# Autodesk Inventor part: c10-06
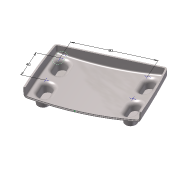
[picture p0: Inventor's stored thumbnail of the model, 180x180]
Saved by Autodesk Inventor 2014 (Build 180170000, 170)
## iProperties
Created: 2010-12
Part Number: c10-06
Material: Generic
Document SubType Name: Modeling
Designer: Thom Tremblay
Density: 1 g/cm^3
Appearance: Generic
Author: Thom Tremblay
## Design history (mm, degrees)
sketch "Sketch1"
  geometry: L1 (-60, -12)-(60, -12); L2 (60, -12)-(60, 12); L3 (60, 12)-(-60, 12); L4 (-60, 12)-(-60, -12); A1 r 350 centre (0, -332.819) between (60, 12) and (-60, 12); A2 r 350 centre (0, 332.819) between (-60, -12) and (60, -12); 3 further points
  constraints: 8 end point, 4 point on circle, 2 centre point, 2 midpoint, 2 parallel, 1 equal radius, 1 horizontal, 1 horizontal alignment, 1 perpendicular, 1 vertical alignment
  dimensions: "d0" = 120 distance of L3.end L2.end; "d1" = 24 distance of L2.end L1.end; "d2" = 350 radius of A1
workplane "Work Plane4"
sketch "Sketch5"
  geometry: L1 (-60, 12)-(-60, -12) reference; L2 (60, -12)-(60, 12) reference; L3 (-58, 10.314)-(-58, -10.314); L4 (58, -10.314)-(58, 10.314); A1 r 350 centre (0, 332.819) between (-60, -12) and (60, -12) reference; A2 r 350 centre (0, -332.819) between (60, 12) and (-60, 12) reference; A3 r 348 centre (0, 332.819) between (-58, -10.314) and (58, -10.314); A4 r 348 centre (0, -332.819) between (58, 10.314) and (-58, 10.314); 1 further point
  constraints: 4 end point, 4 point on circle, 2 centre point, 3 other
  dimensions: "d37" = 2 distance between parallel lines of L2 L4
sketch "Sketch6"
  geometry: L1 (-60, 0)-(60, 0); L2 (60, 0)-(58.843, 22.085); L3 (-60, 0)-(-58.779, 23.307); A1 r 691.758 centre (630.81, -36.204) between (-60, 0) and (-58, -100); A2 r 691.758 centre (-630.81, -36.204) between (58, -100) and (60, 0); 1 further point
  constraints: 6 end point, 4 point on circle, 2 centre point, 2 tangent, 1 horizontal
  dimensions: "d53" = 87 deg angle of L1 L3; "d54" = 87 deg angle of L1 L2 (= d53)
sketch "Sketch7"
  geometry: L1 (17.181, 0)-(12, 0) reference; L2 (15.181, -100)-(10.314, -100) reference; L3 (17.181, 0)-(16.768, 11.838); A1 r 911.322 centre (-893.585, -31.805) between (15.181, -100) and (17.181, 0); 1 further point
  constraints: 2 end point, 2 point on circle, 1 centre point, 1 tangent
  dimensions: "d56" = 88 deg angle of L1 L3
feature "LoftSrf2" sketch "Sketch5", "Sketch6", "Sketch7" dims "d57" = 0, "d58" = 90 deg, "d59" = 0, "d60" = 90 deg, "d61" = 0, "d62" = 90 deg, "d63" = 0, "d64" = 90 deg, "d65" = 0, "d66" = 90 deg
sketch "Sketch2"
  geometry: L1 (-75, -16)-(75, -16); L2 (-75, -60)-(75, -60); A1 r 183.781 centre (0, -183.781) between (75, -16) and (-75, -16); 2 further points
  constraints: 4 end point, 3 point on circle, 1 centre point, 1 coincident, 1 horizontal, 1 parallel
  dimensions: "d5" = 16 distance from line of point (0, 0) L1; "d7" = 60 distance from line of point (0, 0) L2; "d55" = 150 distance of L1.start L1.end
feature "RevolutionSrf1" sketch "Sketch2" dims angle "d8" = 40 deg
patch "Boundary Patch1" dims "d13" = 0, "d67" = 0, "d68" = 0, "d69" = 0, "d70" = 0
workplane "Work Plane1"
sketch "Sketch3"
  geometry: L1 (52, -85)-(52, -73); L2 (38, -73)-(38, -85); A1 r 7 centre (45, -73) between (52, -73) and (38, -73); A2 r 7 centre (45, -85) between (38, -85) and (52, -85); 1 further point
  constraints: 4 end point, 4 point on circle, 4 tangent, 2 centre point, 1 parallel, 1 vertical
  dimensions: "d15" = 12 distance of L1.start L1.end; "d16" = 7 radius of A1; "d50" = 45 horizontal distance of A1.centre point (0, 0); "d51" = 85 vertical distance of point (0, 0) A2.centre
extrude_surface "ExtrusionSrf2" sketch "Sketch3" dims "d19" = 14, "d20" = 5 deg
pattern_linear "Rectangular Pattern1" dims "d23" = 90
workplane "Work Plane2"
feature "Sculpt1"
sketch "Sketch4"
  geometry: L1 (-24.5, 6)-(24.5, 6); L2 (27.5, 3)-(27.5, -3); L3 (24.5, -6)-(-24.5, -6); L4 (-27.5, -3)-(-27.5, 3); A1 r 3 centre (-24.5, 3) between (-24.5, 6) and (-27.5, 3); A2 r 3 centre (24.5, 3) between (27.5, 3) and (24.5, 6); A3 r 3 centre (24.5, -3) between (24.5, -6) and (27.5, -3); A4 r 3 centre (-24.5, -3) between (-27.5, -3) and (-24.5, -6); 6 further points
  constraints: 8 end point, 8 point on circle, 8 tangent, 6 point on line, 4 centre point, 3 equal radius, 2 midpoint, 2 parallel, 1 horizontal, 1 horizontal alignment, 1 perpendicular, 1 vertical alignment
  dimensions: "d28" = 55 distance of point (27.5, -6) point (-27.5, -6); "d29" = 12 distance of point (27.5, 6) point (27.5, -6); "d30" = 3 radius of A1
extrude_surface "ExtrusionSrf6" sketch "Sketch4" dims "d31" = 14, "d32" = 45 deg
patch "Boundary Patch2" dims "d33" = 0, "d34" = 0
fillet "Fillet1" dims "d79" = 4, "d80" = 3, "d81" = 1
feature "Sculpt2"
node "Splitting Plane 1"
shell "Shell1" dims "d83" = 2
split "Split1"
  body "Solid1"
feature "Lip1" dims "d92" = 1, "d93" = 1, "d94" = 0, "d95" = 0, "d96" = 0, "d97" = 0
feature "Lip2" dims "d98" = 1, "d99" = 1, "d100" = 0, "d101" = 0, "d102" = 0, "d103" = 0.5
split "Split3"
  node "Back"
sketch "Sketch9"
  geometry: L1 (50.167, -73)-(50.167, -85) reference; L2 (39.833, -85)-(39.833, -73) reference; L3 (45, -73)-(45, -85); L4 (45, -85)-(39.833, -85); A1 r 5.167 centre (45, -73) between (50.167, -73) and (39.833, -73) reference; A2 r 5.167 centre (45, -85) between (39.833, -85) and (50.167, -85) reference; 5 further points
  constraints: 4 end point, 1 horizontal, 1 midpoint, 1 parallel, 1 perpendicular, 1 vertical, 3 other
  dimensions: "d86" = 90 distance of point (45, -79) point (-45, -79); "d89" = 40 distance of point (45, -79) point (45, -39)
  node "Projected Loop1"
body "Srf2"
body "Srf3"
body "Srf4"
body "Srf5"
body "Srf6"
body "Srf7"
body "Srf8"
body "Srf9"
body "Srf11"
feature "Stitch Surface1"
body "Srf12"
extrude_surface "ExtrusionSrf3"
extrude_surface "ExtrusionSrf4"
extrude_surface "ExtrusionSrf5"
node "Front"
node "Back - Top"
node "Back - Bottom"
other parameters: "d14" = -24, "d52" = -6
